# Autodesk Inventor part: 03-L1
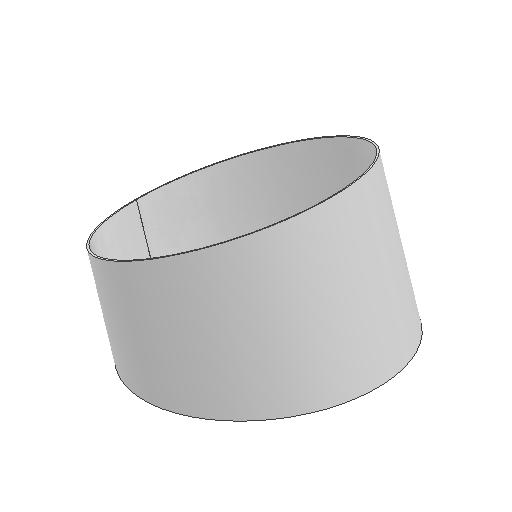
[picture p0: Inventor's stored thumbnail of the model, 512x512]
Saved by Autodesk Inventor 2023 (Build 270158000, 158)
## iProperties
Created: 2023-01
Part Number: 03-L1
Material: Generic
Document SubType Name: Sheet Metal
Designer: Nelson C Agudelo A
Density: 1 g/cm^3
Sheet Metal Rule: Default_mm
Appearance: Default
Flat Pattern Width: 20.59 cm
Flat Pattern Length: 93.3582 cm
Flat Pattern Area: 1922.24 cm^2
Sheet Metal Width: 205,900 mm
Sheet Metal Length: 933,582 mm
Sheet Metal Area: 192224,377 mm^2
Author: Nelson C Agudelo A
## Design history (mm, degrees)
derived "01-Esquema Codo Mitrado.ipt"
  sketch "Sketch1"
    geometry: L1 (0, 0)-(500, 0) reference; L2 (500, 0)-(500, 79.192) reference; L3 (350, 0)-(350, 55.435) reference; L4 (650, 0)-(650, 102.95) reference; L5 (0, 0)-(650, 102.95) reference; L6 (0, 0)-(-500, 0) reference; L7 (-350, 0)-(-350, 55.435) reference; L8 (-650, 0)-(-650, 102.95) reference; L9 (-500, 0)-(-650, 0) reference; L10 (0, 0)-(-650, 102.95) reference; L11 (-500, 0)-(-500, 79.192) reference; L12 (0, 0)-(451.057, 229.825) reference; L13 (500, 79.192)-(451.057, 229.825) reference; L14 (0, 0)-(475.528, 154.508) reference; L15 (650, 0)-(1150, 0) reference; L16 (500, 0)-(1000, 0) reference; L17 (1000, 0)-(1500, 0) reference; 1 further point
workplane "Work Plane1"
node "Contour Flange1"
  sketch "Sketch2"
    geometry: L1 (150, 0.05)-(150, -0.05); A1 r 150 centre (0, 0) between (150, 0.05) and (150, -0.05); 3 further points
    constraints: 2 end point, 2 point on circle, 1 centre point, 1 coincident, 1 midpoint, 1 vertical
    dimensions: "d22" = 150 radius of A1 (= 0.5 x ODtuberia); "d23" = 0.1 distance of L1.start L1.end
sketch "Sketch3"
  geometry: L1 (650, 102.95)-(364.683, 10.245) reference; L2 (0, 0)-(650, 102.95); L3 (0, 0)-(559.105, 382.696); L4 (586.373, 298.772)-(301.057, 206.067) reference; L5 (559.105, 382.696)-(586.373, 298.772); L6 (0, 0)-(677.269, 19.026); L7 (677.269, 19.026)-(650, 102.95); L8 (0, 0)-(586.373, 298.772)
  constraints: 12 end point, 2 point on line, 1 collinear, 1 perpendicular
cut "Cut1" sketch "Sketch3" dims "d24" = 2.5 (= Thickness), "d25" = 0
body "Solid1"
face "Plate1" dims "d7" = 2.5 (= Thickness), "d10" = 2.5 (= BendReliefWidth), "d11" = 1.25 (= BendReliefDepth), "d12" = 5 (= MinimumRemnant), "d15" = 2.5 (= TransitionRadius), "d16" = 205.89977 (= L1 + 2 x Recorte), "d17" = 2.5 (= BendRadius), "d18" = 0.5, "d19" = 10 (= CornerReliefSize), "d20" = 2.5 (= GapSize), "d21" = 2.5 (= JacobiRadiusSize), "SeamGap" = 0.01
bend "Bend1" dims "d7" = 2.5 (= Thickness), "d10" = 2.5 (= BendReliefWidth), "d11" = 1.25 (= BendReliefDepth), "d12" = 5 (= MinimumRemnant), "d15" = 2.5 (= TransitionRadius), "d17" = 2.5 (= BendRadius), "d18" = 0.5, "SeamGap" = 0.01
feature "Corner1" dims "d18" = 0.5, "d19" = 10 (= CornerReliefSize), "d20" = 2.5 (= GapSize), "d21" = 2.5 (= JacobiRadiusSize)
feature "Definition1"
other parameters: "Thickness" = 2.5 (derived), "BendRadius" = 2.5 (= Thickness), "BendReliefWidth" = 2.5 (= Thickness), "BendReliefDepth" = 1.25 (= 0.5 x Thickness), "MinimumRemnant" = 5 (= 2 x Thickness), "TransitionRadius" = 2.5 (= BendRadius), "JacobiRadiusSize" = 2.5 (= BendRadius), "GapSize" = 2.5 (= Thickness), "d2" = 79.19222, "d3" = 180 deg, "DL1" = 18 deg, "d13" = 158.38444, "L2" = 79.19222, "L1" = 158.38444, "Recorte" = 23.75767, "D" = 180 deg, "DL2" = 9 deg, "d14" = 23.75767, "BendRadius" = 2.5, "BendReliefDepth" = 1.25, "BendReliefWidth" = 2.5, "D" = 180 deg, "DL1" = 18 deg, "DL2" = 9 deg, "GapSize" = 2.5, "JacobiRadiusSize" = 2.5, "L1" = 158.38444, "L2" = 79.19222, "MinimumRemnant" = 5, "Recorte" = 23.75767, "Thickness" = 2.5, "TransitionRadius" = 2.5
